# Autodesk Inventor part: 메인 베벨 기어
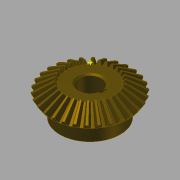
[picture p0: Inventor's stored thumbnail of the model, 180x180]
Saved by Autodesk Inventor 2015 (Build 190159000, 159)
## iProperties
Created: 2014-10
Part Number: 메인 베벨 기어
Material: 강철, 탄소
Document SubType Name: Modeling
Designer: KYOUNG IL JANG
Categories: <?xml version="1.0" encoding="UTF-16"?> <MemberInstance><Categories><FamilyTemplate><FamilyTemplateParameter ValueType="xs:double" Id="1" ObjectReferenceKey="da
Mass: 269.926 g
Surface Area: 108.837 cm^2
Volume: 34.2981 cm^3
Density: 7.87 g/cm^3
Appearance: Brindle
CustomPartVersion: 1
Author: SeoGD™ [www.esajin.kr]
Revision Number: 1
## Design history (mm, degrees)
node "맨 위 점"
node "메쉬 평면2"
sketch "톱니 본체 스케치"
  geometry: L1 (0, 0)-(28.669, -21.997); L2 (28.669, -21.997)-(31.109, -18.336); L3 (31.109, -18.336)-(0, 0); L4 (30, -20)-(0, 0); L5 (17.219, -13.212)-(18.685, -11.013); L6 (28.669, -21.997)-(17.219, -13.212); L7 (31.109, -18.336)-(18.685, -11.013); L8 (0, -39.387)-(0, 6.564) reference; L9 (0, -20)-(31.109, -20)
  constraints: 16 end point, 4 point on line, 3 perpendicular, 2 collinear, 1 horizontal alignment, 1 vertical alignment
  dimensions: "d0" = 60 diameter of L4.start L8 (= da_de); "d1" = 57.33744 diameter of L1.end L8 (= da_dfe); "d2" = 62.2188 diameter of L2.end L8 (= da_dae); "d3" = 14.4 distance between parallel lines of L2 L5 (= da_b); "d4" = 18.3359 vertical distance of L2.end L1.start (= da_ve)
revolve "톱니 본체" sketch "톱니 본체 스케치" stored, may be unused: angle "d5" = 90 deg
node "시작점"
node "톱니 평면"
sketch "시작 스케치"
  geometry: L1 (0, -23.505)-(0, 10.645) reference; L2 (-0.709, -2.928)-(0.709, -2.928); A1 r 19.188 centre (-19.457, -7.014) between (-0.709, -2.928) and (-3.232, 3.229); A2 r 19.188 centre (19.457, -7.014) between (3.232, 3.229) and (0.709, -2.928); A3 r 57.403 centre (0, -54.083) between (3.232, 3.229) and (-3.232, 3.229); 1 further point
  constraints: 6 point on circle, 3 centre point, 3 symmetric about line, 2 end point, 1 coincident, 1 perpendicular, 1 other
  dimensions: "d7" = 19.18795 radius of A1 (= fd_rr); "d8" = 19.45712 horizontal distance of point (0, -54.083) A1.centre (= fd_x); "d9" = 47.06905 vertical distance of point (0, -54.083) A1.centre (= fd_y); "d57" = 57.40327 radius of A3 (= 0.5 x fd_dva + 0.3 x da_he); "d58" = 51.15527 distance from line of A3.centre L2 (= 0.5 x fd_dva - 1.12 x da_he)
node "끝점"
  node "끝 평면"
sketch "3D 스케치 오른쪽"
  node "Helical Curve Right" dims "d65" = 229.90621 (computed from da_dm, da_delta, da_beta), "d66" = 31.5, "d67" = 60 (= da_de), "d68" = -9.82794 (= -da_delta), "d69" = 8.10972 (computed from fd_loft, da_delta)
node "끝 평면 오른쪽"
sketch "끝 스케치 오른쪽"
  geometry: L1 (0, -41.54)-(0, 13.178) reference; L2 (-0.422, -1.69)-(0.422, -1.69); A1 r 11.427 centre (-11.587, -4.123) between (-0.422, -1.69) and (-1.925, 1.977); A2 r 11.427 centre (11.587, -4.123) between (1.925, 1.977) and (0.422, -1.69); A3 r 34.184 centre (0, -32.153) between (1.925, 1.977) and (-1.925, 1.977); 1 further point
  constraints: 6 point on circle, 3 centre point, 3 symmetric about line, 2 end point, 1 coincident, 1 perpendicular, 1 other
  dimensions: "d70" = 11.58699 horizontal distance of A3.centre A1.centre (computed from fd_x, fd_ratio); "d71" = 28.03028 vertical distance of point (0, -32.153) A1.centre (computed from fd_y, fd_ratio); "d72" = 11.4267 radius of A1 (computed from fd_rr, fd_ratio); "d73" = 30.46369 distance from line of point (0, -32.153) L2 (computed from d58, fd_ratio); "d74" = 34.18446 radius of A3 (computed from d57, fd_ratio)
feature "로프트 오른쪽" sketch "끝 스케치 오른쪽" dims "d75" = 0, "d77" = 0, "d79" = 0, "d80" = 90 deg, "d85" = 20, "d92" = 90 deg, "d93" = 90 deg, "da_teethtype" = 0 [user parameter]
sketch "3D 스케치 왼쪽"
  node "Helical Curve Left" dims "d26" = 229.90621 (computed from da_dm, da_delta, da_beta), "d27" = 8.10972 (computed from fd_loft, da_delta), "d28" = 60 (= da_de), "d29" = -9.82794 (= -da_delta)
node "끝 평면 왼쪽"
sketch "끝 스케치 왼쪽" dims "d56" = 10.3728 (derived)
  geometry: L1 (0, -43.753)-(0, 15.405) reference; L2 (-0.422, -1.678)-(0.422, -1.678); A1 r 11.427 centre (-11.587, -4.111) between (-0.422, -1.678) and (-1.925, 1.988); A2 r 11.427 centre (11.587, -4.111) between (1.925, 1.988) and (0.422, -1.678); A3 r 34.184 centre (0, -32.142) between (1.925, 1.988) and (-1.925, 1.988); 2 further points; 1 other entity
  constraints: 6 point on circle, 3 centre point, 3 symmetric about line, 2 end point, 1 coincident, 2 other
  dimensions: "d30" = 11.4267 radius of A1 (computed from fd_rr, fd_ratio); "d31" = 11.58699 horizontal distance of point (0, -32.142) A1.centre (computed from fd_x, fd_ratio); "d32" = 28.03028 vertical distance of A1.centre point (0, -32.142) (computed from fd_y, fd_ratio); "d61" = 34.18446 radius of A3 (computed from d57, fd_ratio); "d62" = 30.46369 distance from line of point (0, -32.142) L2 (computed from d58, fd_ratio)
feature "로프트 왼쪽" sketch "끝 스케치 왼쪽" dims "d35" = 0, "d37" = 0, "d39" = 0, "d40" = 90 deg, "d84" = 10, "d90" = 90 deg, "d91" = 90 deg, "da_teethtype" = 0 [user parameter]
sketch "본체 스케치"
  geometry: L1 (0, -35.038)-(0, -19.531) reference; L2 (28.669, -21.997)-(17.219, -13.212) reference; L3 (17.219, -13.212)-(0, -13.212); L4 (28.669, -21.997)-(0, -21.997)
  constraints: 4 end point, 2 perpendicular, 2 point on line
revolve "본체 고정" sketch "본체 스케치" stored, may be unused: angle "d46" = 90 deg
feature "피치 지름" dims angle "d47" = 90 deg
sketch "스케치8"
  geometry: C1 r 22.5 at (0, 0); 1 further point
  constraints: 1 centre point, 1 coincident
  dimensions: "d94" = 45 diameter of C1
extrude "돌출1" join sketch "스케치8" distance "d95" = 13; taper "d96" = 0 deg
sketch "스케치9"
  geometry: 1 further point
hole "구멍1" sketch "스케치9" at (0, 0) diameter "d97" = 17; stored, may be unused: countersink angle "d101" = 90 deg, drill point angle "d103" = 118 deg; dims "d98" = 6, "d99" = 4, "d100" = 2, "d102" = 8
sketch "스케치10"
  geometry: L1 (8.124, 2.5)-(10.8, 2.5); L2 (10.8, 2.5)-(10.8, -2.5); L3 (10.8, -2.5)-(8.124, -2.5); A1 r 8.5 centre (0, 0) between (8.124, 2.5) and (8.124, -2.5) reference; 1 further point
  constraints: 6 end point, 2 parallel, 2 point on circle, 1 horizontal, 1 perpendicular
  dimensions: "d104" = 5 distance of L1.end L2.end; "d112" = 19.3 dimension on A1 L2
extrude "돌출2" cut sketch "스케치10" stored distance "d106" = 10; taper "d107" = 0 deg
chamfer "모따기1" distance "d108" = 1; stored, may be unused: second distance "d109" = 2, angle "d110" = 45 deg
fillet "모깎기1" dims "d111" = 2
body "Solid1"
feature "로프트" dims "d17" = 0, "d18" = 90 deg, "d19" = 0, "d20" = 90 deg, "d89" = 0, "da_teethtype" = 0 [user parameter]
pattern_circular "원형 패턴" dims angle "d22" = 360 deg, "d88" = 0, "da_teethtype" = 0 [user parameter]
pattern_circular "원형 패턴 오른쪽" dims angle "d82" = 360 deg, "da_teethtype" = 0 [user parameter]
pattern_circular "원형 패턴 왼쪽" dims angle "d42" = 360 deg, "da_teethtype" = 0 [user parameter]
sketch "끝 스케치"
  geometry: L1 (0, -15.359)-(0, 6.983) reference; L2 (-0.422, -1.69)-(0.422, -1.69); A1 r 11.427 centre (-11.587, -4.123) between (-0.422, -1.69) and (-1.925, 1.977); A2 r 11.427 centre (11.587, -4.123) between (1.925, 1.977) and (0.422, -1.69); A3 r 34.184 centre (0, -32.153) between (1.925, 1.977) and (-1.925, 1.977); 1 further point
  constraints: 6 point on circle, 3 centre point, 3 symmetric about line, 2 end point, 1 coincident, 1 other
  dimensions: "d12" = 11.4267 radius of A1 (computed from fd_rr, fd_ratio); "d15" = 11.58699 horizontal distance of A1.centre point (0, -32.153) (computed from fd_x, fd_ratio); "d16" = 28.03028 vertical distance of A1.centre point (0, -32.153) (computed from fd_y, fd_ratio); "d59" = 34.18446 radius of A3 (computed from d57, fd_ratio); "d60" = 30.46369 distance from line of A3.centre L2 (computed from d58, fd_ratio)
sketch "Sketch6"
  geometry: L1 (30, -20)-(0, 0) reference; L2 (0, -37.8)-(0, 6.3) reference
body "Srf1"
other parameters: "da_b" = 14.4 [user parameter; used in 2 equation terms], "da_de" = 60 [user parameter; used in 4 equation terms], "da_dae" = 62.2188 [user parameter; used in 2 equation terms], "da_dfe" = 57.33744 [user parameter; used in 1 equation term], "da_le" = 36.05551 [user parameter; used in 1 equation term], "da_omega" = 90 deg [user parameter; used in 1 equation term], "da_beta" = 0 [user parameter; used in 2 equation terms], "da_delta" = 9.82794 [user parameter; used in 8 equation terms], "da_alpha" = 20 deg [user parameter; used in 2 equation terms], "da_he" = 4.4 [user parameter; used in 4 equation terms], "da_ve" = 18.3359 [user parameter; used in 1 equation term], "fd_dv" = 108.16654 (computed from da_de, da_delta) [user parameter; used in 1 equation term], "fd_dva" = 112.16654 (computed from da_dae, da_delta) [user parameter; used in 3 equation terms], "fd_dvb" = 101.6433 (computed from fd_dv, da_alpha) [user parameter; used in 2 equation terms], "da_zv" = 540.83269 [user parameter; used in 1 equation term], "fd_loft" = 14.62 (= da_b + 0.05 x da_he) [user parameter; used in 4 equation terms], "fd_ratio" = 5.95514 (computed from da_le, fd_loft) [user parameter; used in 15 equation terms], "fd_rr" = 19.18795 (computed from fd_dd, fd_dvb) [user parameter; used in 6 equation terms], "fd_angle" = 0.29367 (computed from da_zv) [user parameter; used in 4 equation terms], "fd_x1" = 1.58802 (computed from da_dvw, fd_angle) [user parameter; used in 1 equation term], "fd_y1" = 54.05995 (computed from da_dvw, fd_angle) [user parameter; used in 1 equation term], "fd_x2" = 17.8691 (computed from fd_rr, fd_angle2, fd_angle) [user parameter; used in 1 equation term], "fd_y2" = 6.9909 (computed from fd_rr, fd_angle2, fd_angle) [user parameter; used in 1 equation term], "fd_x" = 19.45712 (= fd_x1 + fd_x2) [user parameter; used in 4 equation terms], "fd_y" = 47.06905 (= fd_y1 - fd_y2) [user parameter; used in 4 equation terms], "fd_angle2" = 3.43555 (computed from fd_dvb, fd_dd, da_alpha) [user parameter; used in 2 equation terms], "fd_dd" = 108.64654 (= fd_dva - 0.8 x da_he) [user parameter; used in 2 equation terms], "da_dvw" = 108.16654 [user parameter; used in 2 equation terms], "d11" = 14.62 (= fd_loft), "da_dm" = 48.01848 [user parameter; used in 2 equation terms], "da_x" = 0 [user parameter], "da_m" = 2 [user parameter], "d48" = 0, "d49" = 0, "d50" = 90 deg (= da_omega), "d51" = 6 deg (computed from da_z), "d52" = 0, "d53" = 0, "d54" = 0
